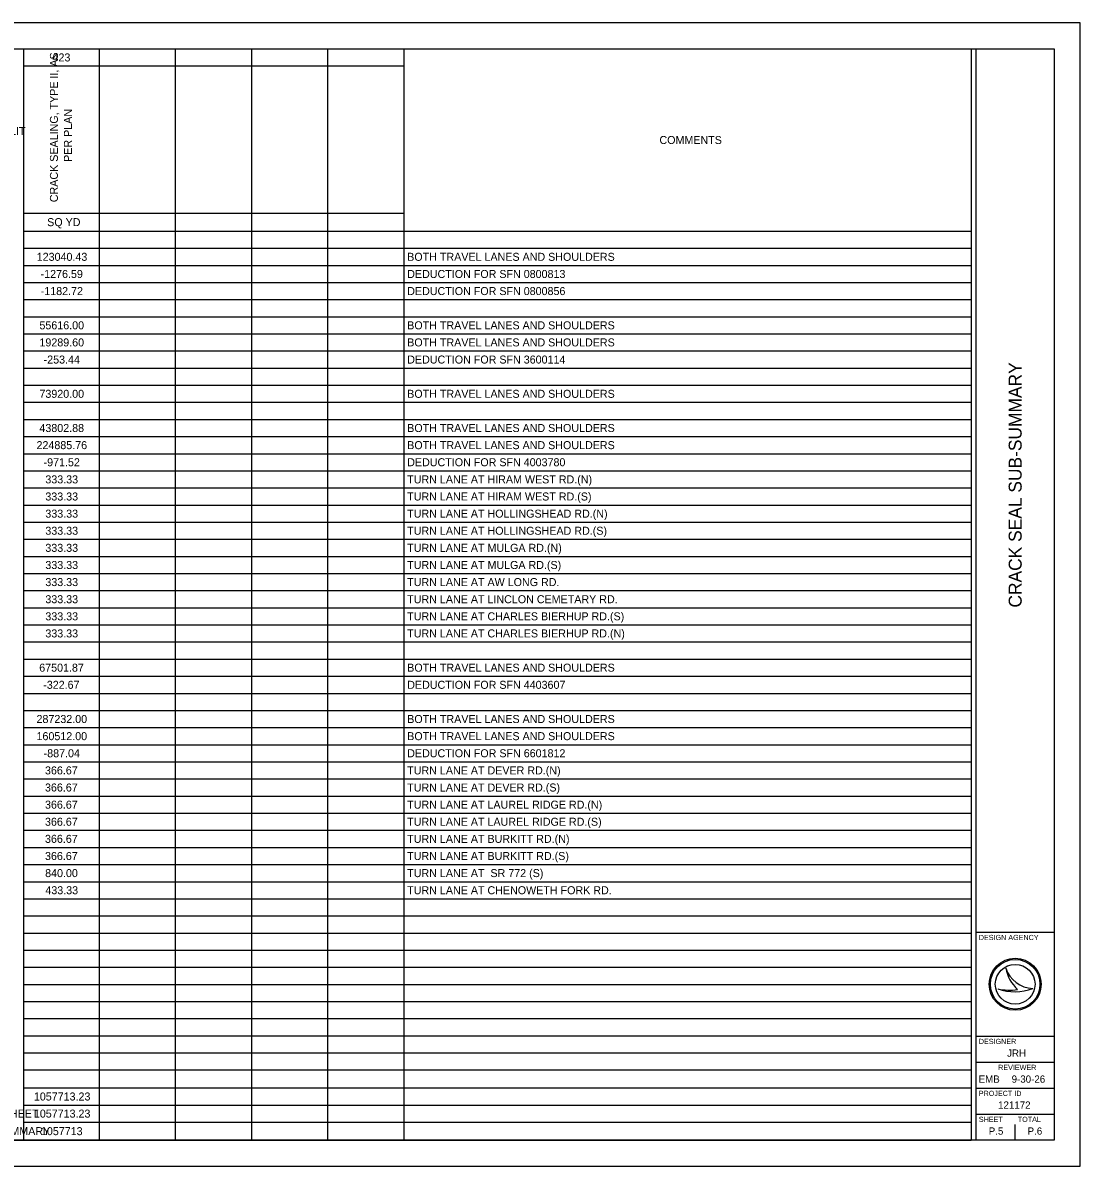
# Model space of a CAD drawing. Extents: x 0 to 34, y 0 to 22.
# Drawn here: x 13.66 to 34, y 0 to 22 of the extents above; entities that cross this region are included whole.
import ezdxf

# ---------------------------------------------------------------- set-up
doc = ezdxf.new("R2010")
doc.units = 0
for name, color, linetype in [('Default', 7, 'Continuous'), ('SH_Border', 7, 'Continuous'), ('SH_Cut_Line', 7, 'Continuous'), ('SH_Data', 7, 'Continuous')]:
    doc.layers.add(name, color=color, linetype=linetype)

msp = doc.modelspace()

# ---------------------------------------------------------------- linework, layer by layer
at = {"layer": 'Default'}
for p, q in [((12.409, 21.5), (13.666, 21.5)), ((13.644, 21.5), (31.905, 21.5)), ((13.666, 21.5), (13.666, 0.5)), ((15.121, 21.5), (15.121, 0.5)), ((16.587, 21.5), (16.587, 0.5)), ((18.053, 21.5), (18.053, 0.5)), ((19.519, 21.5), (19.519, 0.5)), ((20.985, 21.5), (20.985, 0.5)), ((31.905, 21.5), (31.905, 0.5)), ((13.666, 21.171), (20.985, 21.171)), ((13.666, 18.338), (20.985, 18.338)), ((13.666, 17.992), (31.905, 17.992)), ((13.666, 17.662), (31.905, 17.662)), ((13.666, 17.333), (31.905, 17.333)), ((13.666, 17.004), (31.905, 17.004)), ((13.666, 16.674), (31.905, 16.674)), ((13.666, 16.345), (31.905, 16.345)), ((13.666, 16.015), (31.905, 16.015)), ((13.666, 15.686), (31.905, 15.686)), ((13.666, 15.356), (31.905, 15.356)), ((13.666, 15.027), (31.905, 15.027)), ((13.666, 14.698), (31.905, 14.698)), ((13.666, 14.368), (31.905, 14.368)), ((13.666, 14.039), (31.905, 14.039)), ((13.666, 13.709), (31.905, 13.709)), ((13.666, 13.38), (31.905, 13.38)), ((13.666, 13.051), (31.905, 13.051)), ((13.666, 12.721), (31.905, 12.721)), ((13.666, 12.392), (31.905, 12.392)), ((13.666, 12.062), (31.905, 12.062)), ((13.666, 11.733), (31.905, 11.733)), ((13.666, 11.404), (31.905, 11.404)), ((13.666, 11.074), (31.905, 11.074)), ((13.666, 10.745), (31.905, 10.745)), ((13.666, 10.415), (31.905, 10.415)), ((13.666, 10.086), (31.905, 10.086)), ((13.666, 9.756), (31.905, 9.756)), ((13.666, 9.427), (31.905, 9.427)), ((13.666, 9.098), (31.905, 9.098)), ((13.666, 8.768), (31.905, 8.768)), ((13.666, 8.439), (31.905, 8.439)), ((13.666, 8.109), (31.905, 8.109)), ((13.666, 7.78), (31.905, 7.78)), ((13.666, 7.451), (31.905, 7.451)), ((13.666, 7.121), (31.905, 7.121)), ((13.666, 6.792), (31.905, 6.792)), ((13.666, 6.462), (31.905, 6.462)), ((13.666, 6.133), (31.905, 6.133)), ((13.666, 5.804), (31.905, 5.804)), ((13.666, 5.474), (31.905, 5.474)), ((13.666, 5.145), (31.905, 5.145)), ((13.666, 4.815), (31.905, 4.815)), ((13.666, 4.486), (31.905, 4.486)), ((13.666, 4.156), (31.905, 4.156)), ((13.666, 3.827), (31.905, 3.827)), ((13.666, 3.498), (31.905, 3.498)), ((13.666, 3.168), (31.905, 3.168)), ((13.666, 2.839), (31.905, 2.839)), ((13.666, 2.509), (31.905, 2.509)), ((13.666, 2.18), (31.905, 2.18)), ((13.666, 1.851), (31.905, 1.851)), ((13.666, 1.505), (31.905, 1.505)), ((13.666, 1.175), (31.905, 1.175)), ((13.666, 0.846), (31.905, 0.846)), ((1.5, 0.5), (13.666, 0.5)), ((13.644, 0.5), (31.905, 0.5))]:
    msp.add_line(p, q, dxfattribs=at)
at = {"layer": 'SH_Border'}
for p, q in [((32, 0.5), (32, 21.5)), ((32, 4.5), (33.5, 4.5)), ((32, 2.5), (33.5, 2.5)), ((32, 2), (33.5, 2)), ((32, 1.5), (33.5, 1.5)), ((32, 1), (33.5, 1))]:
    msp.add_line(p, q, dxfattribs=at)
msp.add_lwpolyline([(1.5, 21.5), (33.5, 21.5), (33.5, 0.5), (1.5, 0.5)], close=True, dxfattribs=at)
at = {"layer": 'SH_Cut_Line'}
msp.add_lwpolyline([(0, 0), (34, 0), (34, 22), (0, 22)], close=True, dxfattribs=at)
at = {"layer": 'SH_Data'}
for p, q in [((32.567, 3.81), (32.567, 3.81)), ((32.417, 3.41), (32.417, 3.41)), ((32.75, 3.5), (32.75, 3.5)), ((33.087, 3.419), (33.087, 3.419)), ((32.375, 0.675), (32.375, 0.675)), ((32.75, 0.5), (32.75, 0.8))]:
    msp.add_line(p, q, dxfattribs=at)
for radius in [0.5, 0.477, 0.477, 0.382]:
    msp.add_circle((32.75, 3.5), radius, dxfattribs=at)
for centre, radius, start, end in [((33.116, 3.998), 0.58, 198.9257, 198.9319), ((33.347, 3.97), 0.796, 191.6379, 191.6421), ((33.116, 3.998), 0.58, 198.9319, 267.1657), ((33.347, 3.97), 0.796, 191.6421, 226.0947), ((32.739, 4.37), 1.013, 251.4576, 290.0832), ((32.648, 4.654), 1.266, 259.4964, 259.4995), ((32.739, 4.37), 1.013, 251.4527, 251.4576), ((32.648, 4.654), 1.266, 259.4995, 276.6672)]:
    msp.add_arc(centre, radius, start, end, dxfattribs=at)

# ---------------------------------------------------------------- texts
at = {"layer": 'Default'}
for s, p in [('CRACK SEALING, TYPE II, AS ', (14.33, 18.549)), ('PER PLAN', (14.6, 19.325))]:
    msp.add_text(s, height=0.154, rotation=90, dxfattribs=at).set_placement(p)
for s, p in [('423', (14.226, 21.258)), ('PLAN SPLIT', (12.537, 19.842)), ('COMMENTS', (25.905, 19.669)), ('SQ YD', (14.123, 18.088)), ('123040.43', (13.922, 17.421)), ('BOTH TRAVEL LANES AND SHOULDERS', (21.051, 17.421)), ('-1276.59', (13.997, 17.091)), ('DEDUCTION FOR SFN 0800813', (21.051, 17.091)), ('-1182.72', (13.999, 16.762)), ('DEDUCTION FOR SFN 0800856', (21.051, 16.762)), ('55616.00', (13.974, 16.103)), ('BOTH TRAVEL LANES AND SHOULDERS', (21.051, 16.103)), ('19289.60', (13.974, 15.774)), ('BOTH TRAVEL LANES AND SHOULDERS', (21.051, 15.774)), ('-253.44', (14.055, 15.444)), ('DEDUCTION FOR SFN 3600114', (21.051, 15.444)), ('73920.00', (13.974, 14.785)), ('BOTH TRAVEL LANES AND SHOULDERS', (21.051, 14.785)), ('43802.88', (13.974, 14.127)), ('BOTH TRAVEL LANES AND SHOULDERS', (21.051, 14.127)), ('224885.76', (13.918, 13.797)), ('BOTH TRAVEL LANES AND SHOULDERS', (21.051, 13.797)), ('-971.52', (14.054, 13.468)), ('DEDUCTION FOR SFN 4003780', (21.051, 13.468)), ('333.33', (14.088, 13.138)), ('TURN LANE AT HIRAM WEST RD.(N)', (21.051, 13.138)), ('333.33', (14.088, 12.809)), ('TURN LANE AT HIRAM WEST RD.(S)', (21.051, 12.809)), ('333.33', (14.088, 12.479)), ('TURN LANE AT HOLLINGSHEAD RD.(N)', (21.051, 12.479)), ('333.33', (14.088, 12.15)), ('TURN LANE AT HOLLINGSHEAD RD.(S)', (21.051, 12.15)), ('333.33', (14.088, 11.821)), ('TURN LANE AT MULGA RD.(N)', (21.051, 11.821)), ('333.33', (14.088, 11.491)), ('TURN LANE AT MULGA RD.(S)', (21.051, 11.491)), ('333.33', (14.088, 11.162)), ('TURN LANE AT AW LONG RD.', (21.051, 11.162)), ('333.33', (14.088, 10.832)), ('TURN LANE AT LINCLON CEMETARY RD.', (21.051, 10.832)), ('333.33', (14.088, 10.503)), ('TURN LANE AT CHARLES BIERHUP RD.(S)', (21.051, 10.503)), ('333.33', (14.088, 10.174)), ('TURN LANE AT CHARLES BIERHUP RD.(N)', (21.051, 10.174)), ('67501.87', (13.97, 9.515)), ('BOTH TRAVEL LANES AND SHOULDERS', (21.051, 9.515)), ('-322.67', (14.047, 9.185)), ('DEDUCTION FOR SFN 4403607', (21.051, 9.185)), ('287232.00', (13.918, 8.527)), ('BOTH TRAVEL LANES AND SHOULDERS', (21.051, 8.527)), ('160512.00', (13.918, 8.197)), ('BOTH TRAVEL LANES AND SHOULDERS', (21.051, 8.197)), ('-887.04', (14.055, 7.868)), ('DEDUCTION FOR SFN 6601812', (21.051, 7.868)), ('TURN LANE AT DEVER RD.(N)', (21.051, 7.538)), ('366.67', (14.081, 7.538)), ('366.67', (14.081, 7.209)), ('TURN LANE AT DEVER RD.(S)', (21.051, 7.209)), ('TURN LANE AT LAUREL RIDGE RD.(N)', (21.051, 6.879)), ('366.67', (14.081, 6.879)), ('366.67', (14.081, 6.55)), ('TURN LANE AT LAUREL RIDGE RD.(S)', (21.051, 6.55)), ('TURN LANE AT BURKITT RD.(N)', (21.051, 6.221)), ('366.67', (14.081, 6.221)), ('366.67', (14.081, 5.891)), ('TURN LANE AT BURKITT RD.(S)', (21.051, 5.891)), ('TURN LANE AT  SR 772 (S)', (21.051, 5.562)), ('840.00', (14.084, 5.562)), ('433.33', (14.088, 5.232)), ('TURN LANE AT CHENOWETH FORK RD.', (21.051, 5.232)), ('1057713.23', (13.867, 1.263)), ('SUB-SUMMARY THIS SHEET', (11.141, 0.934)), ('1057713.23', (13.867, 0.934)), ('TOTALS CARRIED TO THE GENERAL SUMMARY', (9.433, 0.596)), ('1057713', (14.003, 0.596))]:
    msp.add_text(s, height=0.154, dxfattribs=at).set_placement(p)
at = {"layer": 'SH_Data'}
msp.add_text('CRACK SEAL SUB-SUMMARY', height=0.25, rotation=90, dxfattribs=at).set_placement((32.875, 10.749))
for s, height, p in [('DESIGN AGENCY', 0.1, (32.05, 4.35)), ('DESIGNER', 0.1, (32.05, 2.35)), ('JRH', 0.14, (32.595, 2.105)), ('REVIEWER', 0.1, (32.422, 1.85)), ('EMB', 0.14, (32.047, 1.605)), ('9-30-26', 0.14, (32.682, 1.605)), ('PROJECT ID', 0.1, (32.05, 1.35)), ('121172', 0.14, (32.421, 1.105)), ('SHEET', 0.1, (32.05, 0.85)), ('TOTAL', 0.1, (32.8, 0.85)), ('P.5', 0.14, (32.241, 0.605)), ('P.6', 0.14, (32.989, 0.605))]:
    msp.add_text(s, height=height, dxfattribs=at).set_placement(p)

doc.saveas('drawing.dxf')
